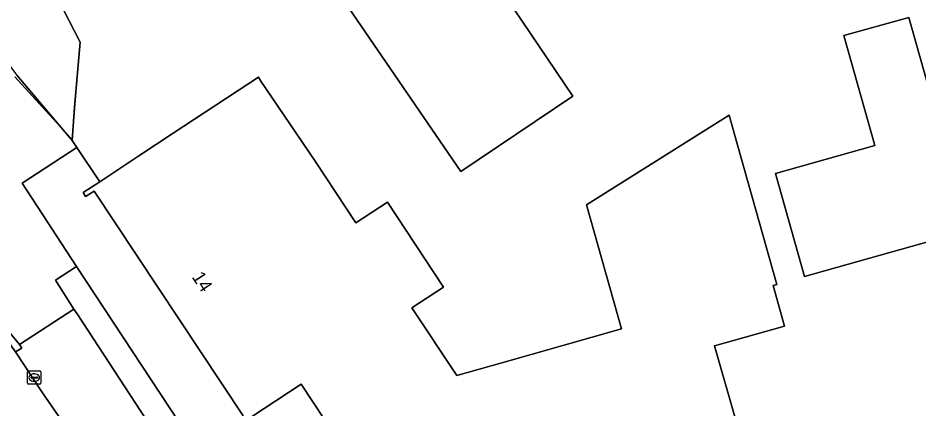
# Model space of a CAD drawing. Extents: x 160030 to 160839, y 385325 to 386450.
# Drawn here: x 160403 to 160470.6, y 385979.3 to 386008.7 of the extents above; entities that cross this region are included whole.
import ezdxf

# ---------------------------------------------------------------- set-up
doc = ezdxf.new("R2010")
doc.units = 0
for name, color, linetype in [('IMGEO_Erf', 7, 'Continuous'), ('IMGEO_Groenvoorziening', 7, 'Continuous'), ('IMGEO_Hek', 7, 'Continuous'), ('IMGEO_Kolk', 7, 'Continuous'), ('IMGEO_Pand', 7, 'Continuous'), ('IMGEO_Pand_nummerreeks', 7, 'Continuous'), ('IMGEO_Parkeervlak_open', 7, 'Continuous'), ('IMGEO_Rijbaan_lokaal_open', 7, 'Continuous'), ('IMGEO_Voetpad_open', 7, 'Continuous')]:
    doc.layers.add(name, color=color, linetype=linetype)

msp = doc.modelspace()

# ---------------------------------------------------------------- linework, layer by layer
at = {"layer": 'IMGEO_Erf'}
msp.add_lwpolyline([(160444.625, 386002.78), (160436.201, 385997.135), (160424.691, 386013.996), (160433.163, 386019.786)], close=True, dxfattribs=at)
for points in [[(160404.764, 386012.501), (160407.646, 386006.836), (160407.227, 386001.951), (160407.063, 385999.441), (160407.399, 385998.937), (160409.118, 385996.358), (160412.057, 385998.296), (160414.64, 386000), (160421.033, 386004.218), (160421.221, 386003.9), (160423.862, 386000), (160425.332, 385997.829), (160428.344, 385993.263), (160430.708, 385994.823), (160434.905, 385988.451), (160432.548, 385986.899), (160435.902, 385981.807), (160439.288, 385982.765), (160448.277, 385985.308), (160445.643, 385994.623), (160454.194, 386000), (160456.338, 386001.348), (160456.719, 386000), (160459.932, 385988.636), (160459.643, 385988.554), (160460.5, 385985.522), (160455.255, 385984.039), (160456.811, 385978.535)], [(160501.395, 386000.338), (160461.993, 385989.233), (160459.809, 385996.979), (160467.274, 385999.083), (160464.951, 386007.325), (160469.83, 386008.7), (160471.536, 386002.647)]]:
    msp.add_lwpolyline(points, dxfattribs=at)
at = {"layer": 'IMGEO_Groenvoorziening'}
msp.add_lwpolyline([(160404.764, 386012.501), (160403.211, 386015.483), (160401.651, 386018.477), (160395.552, 386014.034), (160402.912, 386004.356), (160407.063, 385999.441), (160407.227, 386001.951), (160407.646, 386006.836)], close=True, dxfattribs=at)
at = {"layer": 'IMGEO_Hek'}
for points in [[(160407.063, 385999.441), (160407.107, 386000), (160407.646, 386006.836), (160404.764, 386012.501)], [(160402.753, 386004.235), (160406.917, 385999.66), (160407.063, 385999.441)], [(160407.063, 385999.441), (160407.399, 385998.937)], [(160409.118, 385996.358), (160407.399, 385998.937)]]:
    msp.add_lwpolyline(points, dxfattribs=at)
at = {"layer": 'IMGEO_Kolk'}
for p, q in [((160403.708, 385981.223), (160403.708, 385982.075)), ((160403.783, 385982.149), (160404.635, 385982.149)), ((160404.196, 385981.929), (160404.221, 385981.929)), ((160404.709, 385982.075), (160404.709, 385981.223)), ((160404.635, 385981.149), (160403.783, 385981.149)), ((160403.967, 385981.643), (160403.967, 385981.655)), ((160404.405, 385981.606), (160404.007, 385981.606)), ((160404.01, 385981.692), (160404.408, 385981.692)), ((160404.219, 385981.369), (160404.194, 385981.369)), ((160404.451, 385981.655), (160404.451, 385981.643))]:
    msp.add_line(p, q, dxfattribs=at)
for points in [[(160403.708, 385981.223), (160403.708, 385982.075)], [(160403.783, 385982.149), (160404.635, 385982.149)], [(160404.709, 385982.075), (160404.709, 385981.223)], [(160404.635, 385981.149), (160403.783, 385981.149)]]:
    msp.add_lwpolyline(points, dxfattribs=at)
for centre, radius, start, end in [((160403.785, 385982.073), 0.0765, 91.55205, 178.44795), ((160403.785, 385982.073), 0.0765, 91.55205, 178.44795), ((160404.633, 385982.073), 0.0765, 1.55205, 88.44795), ((160404.633, 385982.073), 0.0765, 1.55205, 88.44795), ((160403.785, 385981.225), 0.0765, 181.55205, 268.44795), ((160403.785, 385981.225), 0.0765, 181.55205, 268.44795), ((160404.007, 385981.652), 0.0403, 85.87752, 175.75265), ((160404.004, 385981.642), 0.0366, 178.93798, 274.71019), ((160404.408, 385981.649), 0.043, 264.86636, 352.45326), ((160404.412, 385981.654), 0.0386, 1.73085, 96.63898), ((160404.633, 385981.225), 0.0765, 271.55205, 358.44795), ((160404.633, 385981.225), 0.0765, 271.55205, 358.44795)]:
    msp.add_arc(centre, radius, start, end, dxfattribs=at)
for centre, major_axis, ratio, start_param, end_param in [((160404.195, 385981.649), (-0.387, 0.002), 0.722429, 4.712389, 7.853982), ((160404.22, 385981.649), (-0.39, 0.002), 0.717154, 1.570796, 4.712389)]:
    msp.add_ellipse(centre, major_axis=major_axis, ratio=ratio, start_param=start_param, end_param=end_param, dxfattribs=at)
at = {"layer": 'IMGEO_Pand'}
msp.add_lwpolyline([(160444.625, 386002.78), (160433.163, 386019.786), (160424.691, 386013.996), (160436.201, 385997.135)], close=True, dxfattribs=at)
for points in [[(160471.536, 386002.647), (160469.83, 386008.7), (160464.951, 386007.325), (160467.274, 385999.083), (160459.809, 385996.979), (160461.993, 385989.233), (160501.395, 386000.338)], [(160456.811, 385978.535), (160455.255, 385984.039), (160460.5, 385985.522), (160459.643, 385988.554), (160459.932, 385988.636), (160456.719, 386000), (160456.338, 386001.348), (160454.194, 386000), (160445.643, 385994.623), (160448.277, 385985.308), (160439.288, 385982.765), (160435.902, 385981.807), (160432.548, 385986.899), (160434.905, 385988.451), (160430.708, 385994.823), (160428.344, 385993.263), (160425.332, 385997.829), (160423.862, 386000), (160421.221, 386003.9), (160421.033, 386004.218), (160414.64, 386000), (160412.057, 385998.296), (160409.118, 385996.358), (160407.883, 385995.543), (160408.059, 385995.258), (160408.713, 385995.647), (160419.876, 385978.772)], [(160419.559, 385978.089), (160424.226, 385981.167), (160426.915, 385977.091)]]:
    msp.add_lwpolyline(points, dxfattribs=at)
at = {"layer": 'IMGEO_Parkeervlak_open'}
msp.add_lwpolyline([(160412.613, 385978.512), (160407.417, 385986.438), (160407.182, 385986.788), (160403.091, 385984.135), (160403.27, 385983.86), (160402.815, 385983.572), (160404.768, 385980.577), (160408.561, 385975.092)], dxfattribs=at)
at = {"layer": 'IMGEO_Rijbaan_lokaal_open'}
for points in [[(160401.823, 385985.689), (160403.091, 385984.135), (160407.182, 385986.788), (160405.816, 385988.972), (160407.383, 385989.993), (160403.297, 385996.242), (160407.399, 385998.937), (160407.063, 385999.441), (160402.912, 386004.356)], [(160400.475, 385978.065), (160407.185, 385967.834), (160410.294, 385963.178), (160415.771, 385954.973), (160416.233, 385954.281), (160420.355, 385948.051), (160424.467, 385950.771), (160424.019, 385951.445), (160421.957, 385954.628), (160421.745, 385955.056), (160412.791, 385968.568), (160410.962, 385971.347), (160408.687, 385974.694), (160408.561, 385975.092), (160404.768, 385980.577), (160402.815, 385983.572), (160402.309, 385984.273), (160402.091, 385984.502)]]:
    msp.add_lwpolyline(points, dxfattribs=at)
at = {"layer": 'IMGEO_Voetpad_open'}
for points in [[(160419.876, 385978.772), (160408.713, 385995.647), (160408.059, 385995.258), (160407.883, 385995.543), (160409.118, 385996.358), (160407.399, 385998.937), (160403.297, 385996.242), (160407.383, 385989.993), (160424.868, 385963.428)], [(160407.383, 385989.993), (160405.816, 385988.972), (160407.182, 385986.788), (160407.417, 385986.438), (160412.613, 385978.512)], [(160464.136, 385892.004), (160462.447, 385896.161), (160459.682, 385900.262), (160459.55, 385900.64), (160459.276, 385904.104), (160458.885, 385905.233), (160457.496, 385907.331), (160439.216, 385934.935), (160437.557, 385937.447), (160431.847, 385945.931), (160430.276, 385948.273), (160427.012, 385949.858), (160431.791, 385953.009), (160424.868, 385963.428), (160407.383, 385989.993)], [(160402.091, 385984.502), (160402.309, 385984.273), (160402.815, 385983.572), (160403.27, 385983.86), (160403.091, 385984.135), (160401.823, 385985.689)], [(160426.915, 385977.091), (160424.226, 385981.167), (160419.559, 385978.089)]]:
    msp.add_lwpolyline(points, dxfattribs=at)

# ---------------------------------------------------------------- texts
at = {"layer": 'IMGEO_Pand_nummerreeks'}
msp.add_text('14', height=1, rotation=303.48508, dxfattribs=at).set_placement((160415.992, 385989.211))

doc.saveas('drawing.dxf')
